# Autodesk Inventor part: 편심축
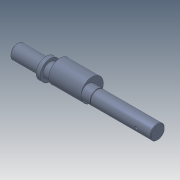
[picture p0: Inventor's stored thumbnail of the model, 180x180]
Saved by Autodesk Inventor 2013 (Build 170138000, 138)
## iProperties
Manager: 한국ATC센터
Company: 한국ATC센터
Created: 2014-10
Part Number: 편심축
Document SubType Name: Modeling
Designer: 한국ATC센터
Density: 7.86 g/cm^3
Material: 강, 연강
Mass: 1459.35 g
Surface Area: 294.4 cm^2
Volume: 185.668 cm^3
Author: KYOUNG IL JANG
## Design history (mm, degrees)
sketch "스케치1"
  geometry: L1 (-147, 0)-(147, 0); L2 (-147, 0)-(-147, 12.5); L3 (-147, 12.5)-(-47, 12.5); L4 (-47, 12.5)-(-47, 17.5); L5 (-47, 17.5)-(-40, 17.5); L6 (-40, 17.5)-(-40, 12.5); L7 (-40, 12.5)-(41.65, 12.5); L8 (41.65, 12.5)-(41.65, 11.95); L9 (41.65, 11.95)-(43, 11.95); L10 (43, 11.95)-(43, 12.5); L11 (43, 12.5)-(147, 12.5); L12 (147, 12.5)-(147, 0); L13 (114, 12.5)-(114, 9.1); L14 (114, 9.1)-(139, 9.1); L15 (139, 9.1)-(139, 12.5); L16 (122, -12.5)-(124.5, -12.5); L17 (124.5, -12.5)-(122, -10); L18 (122, -10)-(122, -12.5); L19 (-114, 12.5)-(-114, 9.1); L20 (-114, 9.1)-(-139, 9.1); L21 (-139, 9.1)-(-139, 12.5); L22 (-122, -12.5)-(-122, -10); L23 (-122, -10)-(-119.5, -12.5); L24 (-119.5, -12.5)-(-122, -12.5); 2 further points
  constraints: 48 end point, 11 parallel, 8 perpendicular, 5 collinear, 4 point on line, 1 coincident, 1 horizontal, 1 midpoint, 1 vertical
  dimensions: "d0" = 294 distance of L1.start L1.end (derived); "d1" = 25 diameter of L3 L1; "d2" = 35 diameter of L5 L1; "d3" = 100 distance of L2.end L3.end; "d4" = 187 distance between parallel lines of L12 L6; "d6" = 1.35 distance of L8.end L9.end; "d7" = 23.9 diameter of L9 L1; "d8" = 3.4 distance between parallel lines of L14 L11; "d9" = 8 distance between parallel lines of L15 L12; "d10" = 25 distance of L13.end L14.end; "d11" = 25 diameter of L16 L1 (= d1); "d12" = 25 distance from line of L12 L16.start; "d13" = 45 deg angle of L17 L18; "d14" = 5 diameter of L16.end L18; "d27" = 104 distance between parallel lines of L10 L12; "d32" = 7 distance of L4.end L5.end; "d33" = 8 distance between parallel lines of L2 L21; "d34" = 25 distance between parallel lines of L21 L19; "d35" = 3.4 distance between parallel lines of L3 L20; "d36" = 25 distance from line of L22.start L2; "d37" = 5 diameter of L23.end L22
revolve "회전1" stored, may be unused: angle "d15" = 90 deg
revolve "회전2" stored, may be unused: angle "d16" = 90 deg
revolve "회전3" stored, may be unused: angle "d38" = 90 deg
extrude "돌출1" cut sketch "스케치1" stored distance "d17" = 8; taper "d18" = 0 deg
fillet "모깎기1" dims "d19" = 4
node "작업 평면1"
sketch "스케치2"
  geometry: C1 r 12.5 at (0, 0) reference; C2 r 19.5 at (0, 7); 1 further point
  constraints: 1 centre point, 1 tangent, 1 vertical alignment
  dimensions: "d21" = 7 distance of point (0, 0) C2.centre; "d30" = 39 diameter of C2 (derived)
extrude "돌출2" join sketch "스케치2" distance "d22" = 56; taper "d23" = 0 deg
chamfer "모따기1" distance "d24" = 1; stored, may be unused: second distance "d25" = 2, angle "d26" = 45 deg
node "솔리드1"
